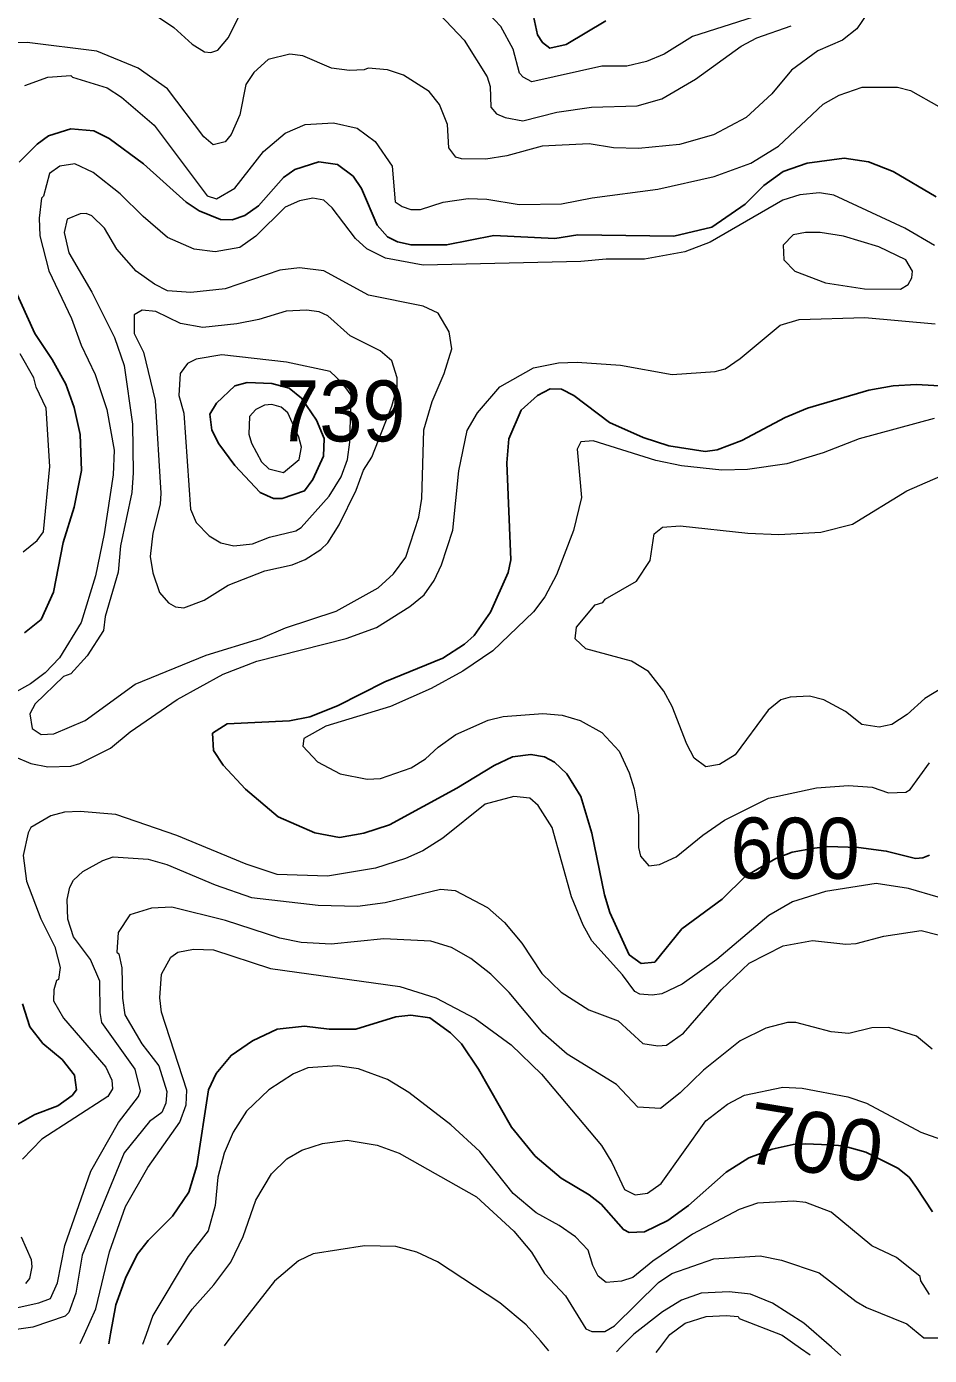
# Model space of a CAD drawing. Extents: x 673.3 to 698.5, y 6984.3 to 7012.3.
# Drawn here: x 695.588 to 696.773, y 6984.271 to 6986.015 of the extents above; entities that cross this region are included whole.
import ezdxf
from ezdxf.enums import TextEntityAlignment as Align

# ---------------------------------------------------------------- set-up
doc = ezdxf.new("R2010")
doc.units = 0
doc.header["$LTSCALE"] = 0.032
doc.layers.add('1', color=7, linetype='Continuous', lineweight=25)
doc.layers.add('2', color=7, linetype='Continuous', lineweight=13)
doc.layers.add('21', color=7, linetype='Continuous')
doc.layers.add('61', color=7, linetype='Continuous')

msp = doc.modelspace()

# ---------------------------------------------------------------- linework, layer by layer
at = {"layer": '1'}
for points in [[(696.2469, 6986.0598), (696.2588, 6986.0042), (696.2653, 6985.9943), (696.2751, 6985.987), (696.2963, 6985.9918), (696.3486, 6986.0229)], [(696.7822, 6985.7918), (696.7259, 6985.825), (696.6936, 6985.8378), (696.6613, 6985.8427), (696.6131, 6985.8361), (696.5815, 6985.825), (696.5562, 6985.8067), (696.5313, 6985.7822), (696.4877, 6985.7521), (696.4377, 6985.7401), (696.3118, 6985.7417), (696.2818, 6985.7369), (696.2014, 6985.7409), (696.1395, 6985.7287), (696.0929, 6985.7287), (696.0751, 6985.7325), (696.0619, 6985.7392), (696.0484, 6985.7546), (696.0276, 6985.8025), (696.0168, 6985.8191), (695.9963, 6985.8343), (695.9718, 6985.8377), (695.9402, 6985.8275), (695.9254, 6985.8172), (695.8928, 6985.7798), (695.8746, 6985.7672), (695.858, 6985.7614), (695.8425, 6985.7621), (695.8146, 6985.7732), (695.7978, 6985.7848), (695.7414, 6985.8349), (695.6965, 6985.8681), (695.6764, 6985.8785), (695.646, 6985.8811), (695.6171, 6985.872), (695.6018, 6985.861), (695.5783, 6985.8373)], [(695.5637, 6985.6908), (695.599, 6985.6125), (695.6218, 6985.5783), (695.6397, 6985.5458), (695.6506, 6985.5151), (695.6586, 6985.48), (695.6602, 6985.4328), (695.6505, 6985.3845), (695.636, 6985.3383), (695.6233, 6985.2729), (695.6073, 6985.2371), (695.5854, 6985.2194)], [(696.4311, 6985.4649), (696.4789, 6985.4576), (696.4946, 6985.4599), (696.5269, 6985.4719), (696.5842, 6985.5022), (696.6132, 6985.5143), (696.6939, 6985.5382), (696.7259, 6985.5438), (696.7558, 6985.5454), (696.8416, 6985.5408)], [(696.7735, 6984.9276), (696.7647, 6984.9244), (696.7553, 6984.9235), (696.7167, 6984.9332), (696.6802, 6984.9379), (696.6397, 6984.939), (696.6226, 6984.9369), (696.5933, 6984.9317), (696.5719, 6984.9236), (696.5321, 6984.9001), (696.5013, 6984.8702), (696.4483, 6984.831), (696.4128, 6984.7875), (696.395, 6984.7857), (696.3793, 6984.7971), (696.354, 6984.8526), (696.3468, 6984.8757), (696.3303, 6984.9565), (696.3156, 6985.005), (696.2973, 6985.0346), (696.2813, 6985.0497), (696.2681, 6985.057), (696.2503, 6985.0601), (696.2259, 6985.0567), (696.202, 6985.0456), (696.1528, 6985.0158), (696.0646, 6984.9678), (696.031, 6984.9568), (695.9991, 6984.951), (695.9666, 6984.9569), (695.9182, 6984.9782), (695.8754, 6985.0143), (695.8461, 6985.046), (695.8337, 6985.0651), (695.8323, 6985.0879), (695.8515, 6985.1), (695.9333, 6985.1041), (695.9599, 6985.1092), (695.9965, 6985.1236), (696.0584, 6985.1554), (696.1346, 6985.1862), (696.1629, 6985.2046), (696.1758, 6985.2159), (696.197, 6985.2469), (696.2202, 6985.2989), (696.2237, 6985.3155), (696.2188, 6985.4428), (696.2213, 6985.4741), (696.2374, 6985.5118), (696.259, 6985.531), (696.2754, 6985.5398), (696.2904, 6985.5395), (696.3066, 6985.5312), (696.3535, 6985.4956), (696.3976, 6985.4759), (696.4311, 6985.4649)], [(695.5829, 6984.7325), (695.5923, 6984.7025), (695.6096, 6984.6805), (695.6347, 6984.6596), (695.6512, 6984.639), (695.6536, 6984.6198), (695.6479, 6984.6122), (695.629, 6984.5987), (695.5989, 6984.5876), (695.5684, 6984.57)], [(695.696, 6984.2865), (695.6984, 6984.2996), (695.7054, 6984.3375), (695.718, 6984.3727), (695.7331, 6984.4037), (695.7479, 6984.4222), (695.7797, 6984.4539), (695.8011, 6984.4854), (695.8118, 6984.5201), (695.827, 6984.6199), (695.8368, 6984.6412), (695.8565, 6984.6651), (695.8847, 6984.6842), (695.917, 6984.6994), (695.9528, 6984.7034), (695.9854, 6984.6993), (696.0202, 6984.6993), (696.073, 6984.7156), (696.0924, 6984.718), (696.1176, 6984.7145), (696.1445, 6984.6946), (696.159, 6984.68), (696.1815, 6984.6469), (696.2246, 6984.571), (696.2556, 6984.533), (696.2899, 6984.5041), (696.3268, 6984.4821), (696.3423, 6984.4698), (696.3717, 6984.4365), (696.3791, 6984.4324), (696.3993, 6984.4337), (696.4301, 6984.4484), (696.4572, 6984.4679), (696.5066, 6984.5116), (696.5364, 6984.5307), (696.567, 6984.5418), (696.5945, 6984.5481), (696.6107, 6984.5489), (696.642, 6984.5478), (696.6602, 6984.5462), (696.6897, 6984.5382), (696.7321, 6984.5172), (696.7468, 6984.5051), (696.7564, 6984.4917), (696.7773, 6984.4599)]]:
    msp.add_lwpolyline(points, dxfattribs=at)
msp.add_lwpolyline([(695.9103, 6985.5469), (695.9327, 6985.5406), (695.9492, 6985.5275), (695.9687, 6985.4985), (695.9786, 6985.4746), (695.9778, 6985.4514), (695.964, 6985.4207), (695.9531, 6985.4061), (695.9235, 6985.3957), (695.9124, 6985.3958), (695.8949, 6985.4036), (695.8613, 6985.4392), (695.8403, 6985.4676), (695.8314, 6985.4855), (695.8288, 6985.5065), (695.8376, 6985.5208), (695.8614, 6985.5438), (695.8776, 6985.5479)], close=True, dxfattribs=at)
at = {"layer": '2'}
for points in [[(695.7585, 6986.0294), (695.7813, 6986.0139), (695.8057, 6985.9919), (695.8216, 6985.982), (695.83, 6985.9812), (695.8392, 6985.9843), (695.853, 6986.0008), (695.8856, 6986.0665)], [(696.6978, 6986.0409), (696.6782, 6986.0122), (696.6592, 6985.9973), (696.6268, 6985.9835), (696.5923, 6985.9579), (696.5667, 6985.9269), (696.5327, 6985.8958), (696.4898, 6985.8731), (696.4451, 6985.8604), (696.3913, 6985.855), (696.3585, 6985.8561), (696.3265, 6985.8615), (696.265, 6985.8581), (696.2186, 6985.8457), (696.1909, 6985.8411), (696.1591, 6985.8415), (696.1517, 6985.8439), (696.1426, 6985.856), (696.1405, 6985.8865), (696.1303, 6985.9131), (696.1168, 6985.93), (696.083, 6985.9513), (696.0619, 6985.9583), (696.0366, 6985.9608), (696.0312, 6985.9584), (696.0119, 6985.9576), (695.9886, 6985.9607), (695.9509, 6985.977), (695.9336, 6985.9788), (695.9053, 6985.9721), (695.8863, 6985.955), (695.876, 6985.9393), (695.8679, 6985.8992), (695.8567, 6985.8734), (695.8488, 6985.8638), (695.8331, 6985.8599), (695.8206, 6985.8704), (695.773, 6985.9336), (695.7346, 6985.9606), (695.6802, 6985.9828), (695.5891, 6985.9943), (695.5616, 6985.9935)], [(696.1225, 6986.04), (696.1628, 6985.9972), (696.1927, 6985.9494), (696.1968, 6985.9364), (696.1975, 6985.9094), (696.2051, 6985.9007), (696.2162, 6985.8957), (696.2395, 6985.8916), (696.2842, 6985.9028), (696.3298, 6985.9094), (696.3896, 6985.9112), (696.4221, 6985.9205), (696.4664, 6985.9462), (696.5264, 6985.9896), (696.5468, 6986.0006), (696.592, 6986.016)], [(696.425, 6985.9789), (696.4021, 6985.9694), (696.3763, 6985.9633), (696.3432, 6985.9632), (696.2515, 6985.9429), (696.24, 6985.9489), (696.2354, 6985.9541), (696.227, 6985.9856), (696.2108, 6986.0151), (696.1941, 6986.0326)], [(696.5421, 6986.0275), (696.4623, 6986.0023), (696.425, 6985.9789)], [(695.5859, 6985.9378), (695.6159, 6985.949), (695.646, 6985.951), (695.6482, 6985.9486), (695.6938, 6985.9346), (695.7129, 6985.9227), (695.7556, 6985.8856), (695.8254, 6985.7929), (695.8374, 6985.7891), (695.8616, 6985.8032), (695.8991, 6985.8514), (695.9275, 6985.8754), (695.9539, 6985.8866), (695.991, 6985.889), (696.0223, 6985.8819), (696.0456, 6985.8644), (696.0681, 6985.8321), (696.0722, 6985.7852), (696.081, 6985.7789), (696.0927, 6985.7752), (696.1051, 6985.7753), (696.1352, 6985.7849), (696.168, 6985.7897), (696.1925, 6985.7889), (696.2349, 6985.7817), (696.2903, 6985.7825), (696.3307, 6985.7906), (696.417, 6985.802), (696.491, 6985.8184), (696.5389, 6985.8361), (696.5754, 6985.8584), (696.6339, 6985.9135), (696.6551, 6985.9252)], [(696.6551, 6985.9252), (696.6853, 6985.9355), (696.7314, 6985.9355), (696.7485, 6985.9314), (696.7856, 6985.9103)], [(696.7801, 6985.7277), (696.741, 6985.7505), (696.6478, 6985.7939), (696.629, 6985.7971), (696.6034, 6985.7945), (696.581, 6985.7872), (696.4857, 6985.7322), (696.4525, 6985.7197), (696.3994, 6985.71), (696.349, 6985.71), (696.3159, 6985.7068), (696.1088, 6985.7019), (696.0595, 6985.7112), (696.0346, 6985.7235), (696.0199, 6985.7369), (695.9891, 6985.7775), (695.9784, 6985.7873), (695.9639, 6985.7898), (695.9466, 6985.7867), (695.9274, 6985.7783), (695.8891, 6985.74), (695.868, 6985.7252), (695.8358, 6985.7198), (695.8082, 6985.7232), (695.7733, 6985.7384), (695.741, 6985.7658), (695.7111, 6985.7958), (695.6756, 6985.8239), (695.6515, 6985.8352), (695.6318, 6985.8321), (695.6182, 6985.8226), (695.6104, 6985.7925), (695.6079, 6985.7901), (695.6047, 6985.7637), (695.6056, 6985.7407), (695.6172, 6985.6947), (695.647, 6985.6321), (695.6596, 6985.5971), (695.678, 6985.5585), (695.6936, 6985.5127), (695.7033, 6985.4594), (695.7017, 6985.4269), (695.6901, 6985.3494), (695.6788, 6985.2944), (695.6596, 6985.2333), (695.6314, 6985.1869), (695.6124, 6985.1672), (695.5932, 6985.1525), (695.5706, 6985.1399)], [(695.5733, 6985.0567), (695.5936, 6985.048), (695.616, 6985.0438), (695.646, 6985.0446), (695.658, 6985.0479), (695.6984, 6985.0683), (695.7241, 6985.0898), (695.7858, 6985.1319), (695.846, 6985.1653), (695.8906, 6985.1822), (696.0077, 6985.2123), (696.0477, 6985.2267), (696.0912, 6985.2541), (696.1099, 6985.2696), (696.1232, 6985.2881), (696.133, 6985.3089), (696.1478, 6985.3544), (696.1554, 6985.432), (696.1666, 6985.485), (696.1799, 6985.5084), (696.2092, 6985.5423), (696.2538, 6985.5674), (696.2864, 6985.5739), (696.3109, 6985.5748), (696.3677, 6985.5708), (696.4355, 6985.5585), (696.4919, 6985.5626), (696.5052, 6985.5661), (696.525, 6985.5794), (696.5775, 6985.6233), (696.6024, 6985.6309), (696.6886, 6985.6335), (696.7808, 6985.6253)], [(695.5838, 6985.3258), (695.6018, 6985.3406), (695.6103, 6985.3523), (695.6186, 6985.438), (695.6137, 6985.5145), (695.6007, 6985.5419), (695.5975, 6985.5542), (695.5797, 6985.5856)], [(696.7794, 6985.5007), (696.6811, 6985.4743), (696.6339, 6985.456), (696.5864, 6985.4413), (696.5346, 6985.4339), (696.5008, 6985.4331), (696.448, 6985.4387), (696.4141, 6985.4459), (696.3321, 6985.4717), (696.3158, 6985.4704), (696.3109, 6985.4607), (696.3167, 6985.3972), (696.3061, 6985.3539), (696.2838, 6985.2958), (696.2685, 6985.267), (696.2536, 6985.2472), (696.2002, 6985.1961), (696.161, 6985.1692), (696.1191, 6985.1465), (696.0659, 6985.1231), (695.9808, 6985.097), (695.9522, 6985.0807), (695.9509, 6985.0707), (695.9699, 6985.0502), (695.9997, 6985.0347), (696.0354, 6985.0276), (696.0527, 6985.0284), (696.0929, 6985.0423), (696.1119, 6985.0543), (696.1285, 6985.0696), (696.1518, 6985.086), (696.1942, 6985.105), (696.2137, 6985.1098), (696.2659, 6985.1139), (696.2911, 6985.1114), (696.3147, 6985.1046), (696.3432, 6985.0888), (696.3662, 6985.0642), (696.3791, 6985.036), (696.3857, 6985.0148), (696.3914, 6984.9808), (696.3915, 6984.9377), (696.3939, 6984.9266), (696.4052, 6984.9136), (696.4192, 6984.9154), (696.4409, 6984.9256), (696.4758, 6984.9541), (696.5045, 6984.9736), (696.5623, 6985.0024), (696.6252, 6985.0161), (696.6673, 6985.0194), (696.6983, 6985.017), (696.7197, 6985.0096), (696.7424, 6985.0105), (696.7483, 6985.0138), (696.7736, 6985.0489)], [(696.7919, 6985.1482), (696.7672, 6985.1335), (696.7443, 6985.1124), (696.7239, 6985.0993), (696.7075, 6985.096), (696.6846, 6985.0995), (696.6633, 6985.1164), (696.6348, 6985.1318), (696.616, 6985.1366), (696.5906, 6985.1352), (696.5782, 6985.1318), (696.5616, 6985.1179), (696.5185, 6985.0595), (696.4977, 6985.0468), (696.48, 6985.0438), (696.4644, 6985.055), (696.4548, 6985.0734), (696.4357, 6985.1231), (696.4248, 6985.1432), (696.4048, 6985.169), (696.3823, 6985.1823), (696.3225, 6985.1985), (696.3085, 6985.2119), (696.3101, 6985.227), (696.3345, 6985.2563), (696.3448, 6985.2596), (696.3479, 6985.2638), (696.3888, 6985.2873), (696.4069, 6985.3143), (696.4121, 6985.3497), (696.423, 6985.3583), (696.4463, 6985.3598), (696.535, 6985.3504), (696.5757, 6985.3485), (696.6307, 6985.3517), (696.6722, 6985.3623), (696.7439, 6985.4061), (696.805, 6985.4325)], [(696.7849, 6984.8728), (696.746, 6984.8841), (696.7035, 6984.8907), (696.6369, 6984.8802), (696.5936, 6984.8666), (696.5627, 6984.8485), (696.4945, 6984.7909), (696.449, 6984.7587), (696.4222, 6984.746), (696.4095, 6984.7441), (696.3933, 6984.7455), (696.3867, 6984.749), (696.3705, 6984.7708), (696.3303, 6984.8154), (696.3187, 6984.8359), (696.3034, 6984.8731), (696.2781, 6984.9643), (696.2597, 6984.9931), (696.2489, 6985.0024), (696.2279, 6985.0047), (696.1903, 6984.9949), (696.1347, 6984.95), (696.1084, 6984.9335), (696.0856, 6984.9235), (696.046, 6984.9108), (695.9831, 6984.9004), (695.9169, 6984.9025), (695.8763, 6984.9158), (695.7854, 6984.9538), (695.7052, 6984.981), (695.6584, 6984.9852), (695.638, 6984.9843), (695.6199, 6984.9795), (695.5936, 6984.9641), (695.59, 6984.9571), (695.5837, 6984.9275), (695.5881, 6984.8937), (695.607, 6984.8441), (695.6252, 6984.8074), (695.6323, 6984.7805), (695.63, 6984.7648), (695.6275, 6984.7634), (695.6237, 6984.7512), (695.6236, 6984.7368), (695.6368, 6984.7139), (695.692, 6984.6494), (695.7001, 6984.6327), (695.7009, 6984.6211), (695.6949, 6984.6109), (695.6083, 6984.5553), (695.5828, 6984.5289)], [(695.5402, 6984.3263), (695.6043, 6984.3402), (695.6195, 6984.3461), (695.6285, 6984.3665), (695.6382, 6984.4154), (695.6725, 6984.5131), (695.7086, 6984.5769), (695.7351, 6984.6109), (695.7375, 6984.6186), (695.7307, 6984.647), (695.6871, 6984.7083), (695.6846, 6984.7212), (695.6845, 6984.7625), (695.6721, 6984.7907), (695.6497, 6984.8205), (695.6422, 6984.8438), (695.6415, 6984.8698), (695.6447, 6984.8856), (695.6497, 6984.8949), (695.6621, 6984.9064), (695.6881, 6984.9209), (695.7018, 6984.9256), (695.7476, 6984.9224), (695.7724, 6984.9157), (695.8358, 6984.8888), (695.8835, 6984.8721), (695.9707, 6984.8621), (696.0226, 6984.8607), (696.0587, 6984.8655), (696.1317, 6984.8833), (696.1507, 6984.8816), (696.1934, 6984.8591), (696.2155, 6984.8394), (696.2385, 6984.8123), (696.2644, 6984.7724), (696.2898, 6984.7478), (696.3263, 6984.7249), (696.3648, 6984.7105), (696.3973, 6984.6808), (696.417, 6984.6774), (696.4283, 6984.6783), (696.4507, 6984.6942), (696.4999, 6984.7509), (696.5367, 6984.786), (696.5813, 6984.8088), (696.6197, 6984.8158), (696.6637, 6984.8109), (696.677, 6984.8117), (696.7134, 6984.8215), (696.7624, 6984.8288), (696.8073, 6984.8175)], [(696.777, 6984.6732), (696.7563, 6984.6903), (696.72, 6984.7017), (696.698, 6984.7011), (696.6675, 6984.6937), (696.6445, 6984.6961), (696.5978, 6984.7082), (696.587, 6984.7082), (696.5585, 6984.7009), (696.5248, 6984.6842), (696.477, 6984.6455), (696.4463, 6984.6158), (696.4203, 6984.5954), (696.3905, 6984.597), (696.3627, 6984.627), (696.2978, 6984.6667), (696.2665, 6984.694), (696.2218, 6984.7475), (696.1978, 6984.7717), (696.1714, 6984.7923), (696.1458, 6984.8067), (696.1187, 6984.8149), (696.0571, 6984.8181), (695.9878, 6984.8109), (695.9487, 6984.8134), (695.9206, 6984.8189), (695.8493, 6984.842), (695.7789, 6984.8597), (695.7522, 6984.8581), (695.7236, 6984.8493), (695.7083, 6984.8262), (695.7066, 6984.8006), (695.7091, 6984.7982), (695.713, 6984.7799), (695.714, 6984.7402), (695.7171, 6984.7183), (695.7395, 6984.6801), (695.7619, 6984.6512), (695.7723, 6984.6175), (695.771, 6984.6022), (695.7658, 6984.5901), (695.7494, 6984.5784), (695.7162, 6984.537), (695.6612, 6984.4028), (695.6528, 6984.353), (695.6436, 6984.3277), (695.6388, 6984.323), (695.5965, 6984.3086), (695.557, 6984.3028)], [(695.6586, 6984.2871), (695.6641, 6984.2993), (695.679, 6984.3326), (695.6969, 6984.4073), (695.7178, 6984.4669), (695.7475, 6984.5178), (695.7893, 6984.5774), (695.7976, 6984.6002), (695.7986, 6984.6192), (695.7651, 6984.7219), (695.7629, 6984.7404), (695.7652, 6984.7716), (695.7776, 6984.7938), (695.7866, 6984.8003), (695.8074, 6984.8043), (695.8336, 6984.8035), (695.9082, 6984.7792), (696.0782, 6984.7555), (696.1255, 6984.7407), (696.1771, 6984.7133), (696.2243, 6984.6791), (696.2642, 6984.6402), (696.3428, 6984.5468), (696.3563, 6984.5245), (696.373, 6984.4892), (696.3869, 6984.4819), (696.4034, 6984.4842), (696.4212, 6984.497), (696.4798, 6984.5791), (696.5085, 6984.6011), (696.5307, 6984.6129), (696.5809, 6984.6235), (696.6064, 6984.6219), (696.6662, 6984.6105), (696.6906, 6984.6023), (696.762, 6984.5641), (696.7878, 6984.5553)], [(696.7737, 6984.3514), (696.7621, 6984.369), (696.7613, 6984.375), (696.73, 6984.3998), (696.6976, 6984.4153), (696.6445, 6984.4592), (696.6111, 6984.472), (696.5948, 6984.4737), (696.5476, 6984.4713), (696.5235, 6984.4627), (696.4624, 6984.4305), (696.4101, 6984.3949), (696.384, 6984.3737), (696.3692, 6984.3686), (696.3491, 6984.3671), (696.3387, 6984.3751), (696.3314, 6984.3895), (696.3255, 6984.4093), (696.3089, 6984.4268), (696.2875, 6984.4418), (696.2569, 6984.4584), (696.2269, 6984.4837), (696.1832, 6984.5387), (696.1453, 6984.5741), (696.0899, 6984.6164), (696.0619, 6984.6332), (696.024, 6984.6473), (695.9961, 6984.6513), (695.9574, 6984.6488), (695.9385, 6984.6409), (695.9061, 6984.6199), (695.8767, 6984.5918), (695.8593, 6984.5644), (695.8476, 6984.5369), (695.8394, 6984.5052), (695.8359, 6984.4682), (695.8263, 6984.4349), (695.8004, 6984.4011), (695.7537, 6984.3237), (695.7449, 6984.2987), (695.7404, 6984.2858)], [(695.773, 6984.2853), (695.7805, 6984.2961), (695.8057, 6984.3322), (695.834, 6984.3641), (695.8564, 6984.3939), (695.8723, 6984.4275), (695.8889, 6984.4752), (695.9095, 6984.5098), (695.93, 6984.5293), (695.9493, 6984.5405), (695.9767, 6984.5494), (696.0089, 6984.5536), (696.0484, 6984.5471), (696.0774, 6984.5367), (696.1787, 6984.4796), (696.2279, 6984.4344), (696.2508, 6984.4068), (696.2681, 6984.3787), (696.2955, 6984.3497), (696.3222, 6984.3062), (696.33, 6984.3028), (696.3472, 6984.3027), (696.3599, 6984.3102), (696.4178, 6984.3672), (696.4352, 6984.3787), (696.4903, 6984.398), (696.5512, 6984.4021), (696.5794, 6984.3964), (696.6288, 6984.3799), (696.6771, 6984.3422), (696.6906, 6984.3343), (696.7439, 6984.3126), (696.766, 6984.2945), (696.7858, 6984.2944)], [(695.5811, 6984.4268), (695.5941, 6984.3972), (695.595, 6984.3874), (695.5918, 6984.3722), (695.5865, 6984.3655)], [(696.2739, 6984.2774), (696.2626, 6984.2904), (696.2442, 6984.3116), (696.2094, 6984.3405), (696.1274, 6984.3941), (696.1004, 6984.407), (696.073, 6984.4142), (696.0317, 6984.4151), (695.9645, 6984.4047), (695.945, 6984.3954), (695.9136, 6984.3689), (695.8549, 6984.2938), (695.8473, 6984.2841)], [(696.6573, 6984.2713), (696.6447, 6984.2822), (696.6087, 6984.3135), (696.5672, 6984.3399), (696.5386, 6984.3516), (696.5105, 6984.3549), (696.4737, 6984.3532), (696.448, 6984.3436), (696.4229, 6984.3283), (696.3854, 6984.299), (696.3688, 6984.2824), (696.3624, 6984.276)], [(696.4147, 6984.2751), (696.4195, 6984.2814), (696.4327, 6984.2986), (696.4529, 6984.3135), (696.4805, 6984.3223), (696.5064, 6984.3239), (696.5224, 6984.3222), (696.5237, 6984.3199), (696.5799, 6984.2977), (696.6041, 6984.2808), (696.6168, 6984.2719)]]:
    msp.add_lwpolyline(points, dxfattribs=at)
for points in [[(696.0499, 6985.2785), (696.0696, 6985.2968), (696.086, 6985.3191), (696.1031, 6985.3713), (696.1072, 6985.3957), (696.1097, 6985.4858), (696.1204, 6985.5232), (696.1365, 6985.5601), (696.1463, 6985.5925), (696.1429, 6985.6148), (696.1283, 6985.639), (696.1086, 6985.6481), (696.0372, 6985.6628), (695.9783, 6985.6945), (695.9466, 6985.6985), (695.9205, 6985.6955), (695.8489, 6985.6709), (695.8039, 6985.666), (695.7732, 6985.6685), (695.7559, 6985.6773), (695.7322, 6985.6941), (695.7064, 6985.723), (695.6904, 6985.7505), (695.674, 6985.7669), (695.6662, 6985.7701), (695.6583, 6985.7695), (695.6415, 6985.7626), (695.6374, 6985.7448), (695.6434, 6985.7184), (695.6737, 6985.6666), (695.7035, 6985.6071), (695.7162, 6985.5706), (695.7271, 6985.4934), (695.728, 6985.4296), (695.7261, 6985.4036), (695.7115, 6985.3337), (695.7082, 6985.2993), (695.6912, 6985.2412), (695.6889, 6985.2228), (695.6678, 6985.1892), (695.646, 6985.1659), (695.6367, 6985.1623), (695.5992, 6985.1262), (695.5926, 6985.1135), (695.5954, 6985.094), (695.6072, 6985.0861), (695.6238, 6985.087), (695.6649, 6985.1047), (695.7308, 6985.152), (695.824, 6985.1902), (695.8951, 6985.2122), (695.9281, 6985.2262), (695.9946, 6985.2482)], [(696.6881, 6985.6712), (696.7353, 6985.6708), (696.7457, 6985.6766), (696.7505, 6985.6853), (696.7513, 6985.6944), (696.7423, 6985.7091), (696.7069, 6985.7261), (696.6608, 6985.7401), (696.6299, 6985.745), (696.6108, 6985.745), (696.5947, 6985.7418), (696.5813, 6985.7284), (696.5821, 6985.7092), (696.5966, 6985.6942), (696.6369, 6985.679)], [(695.901, 6985.3008), (695.937, 6985.309), (695.9539, 6985.3157), (695.9745, 6985.3288), (695.9834, 6985.3378), (695.9984, 6985.3612), (696.0208, 6985.4068), (696.0306, 6985.4329), (696.0415, 6985.45), (696.0678, 6985.5169), (696.0746, 6985.542), (696.0747, 6985.5544), (696.0676, 6985.5765), (696.0525, 6985.5896), (696.0131, 6985.6093), (695.9835, 6985.6358), (695.9721, 6985.6407), (695.9558, 6985.6432), (695.9287, 6985.6416), (695.893, 6985.6307), (695.8641, 6985.6249), (695.8193, 6985.6203), (695.7904, 6985.6256), (695.7579, 6985.6415), (695.74, 6985.6431), (695.7293, 6985.6371), (695.7294, 6985.6124), (695.7418, 6985.5879), (695.757, 6985.5246), (695.7644, 6985.4028), (695.7634, 6985.3885), (695.7539, 6985.3503), (695.7505, 6985.3198), (695.7538, 6985.2982), (695.7625, 6985.2725), (695.7744, 6985.2588), (695.7838, 6985.2538), (695.7947, 6985.2524), (695.8212, 6985.2623), (695.8526, 6985.2821)], [(695.86, 6985.3338), (695.8847, 6985.3363), (695.9069, 6985.3451), (695.9414, 6985.3534), (695.9484, 6985.3576), (695.9855, 6985.3991), (696.001, 6985.4243), (696.0094, 6985.4471), (696.0127, 6985.4699), (696.0144, 6985.5313), (696.0026, 6985.5476), (695.9866, 6985.5624), (695.9295, 6985.5748), (695.8444, 6985.5846), (695.8106, 6985.5787), (695.7995, 6985.5731), (695.7898, 6985.5601), (695.7881, 6985.5311), (695.7945, 6985.508), (695.8033, 6985.382), (695.8106, 6985.3644), (695.8278, 6985.3469), (695.8432, 6985.3379)], [(695.946, 6985.447), (695.9491, 6985.4634), (695.9457, 6985.4762), (695.931, 6985.5083), (695.9224, 6985.5158), (695.9102, 6985.5194), (695.9004, 6985.5185), (695.889, 6985.5128), (695.8809, 6985.5036), (695.8801, 6985.4801), (695.8835, 6985.4686), (695.8967, 6985.4442), (695.9063, 6985.435), (695.9254, 6985.4299)]]:
    msp.add_lwpolyline(points, close=True, dxfattribs=at)

# ---------------------------------------------------------------- texts
at = {"layer": '21', "width": 0.95}
msp.add_text('739', height=0.08, dxfattribs=at).set_placement((695.916, 6985.4708))
at = {"layer": '61', "width": 0.95}
msp.add_text('600', height=0.08, rotation=359.816, dxfattribs=at).set_placement((696.5969, 6984.897), align=Align.CENTER)
at = {"layer": '61'}
msp.add_text('700', height=0.08, rotation=350.744, dxfattribs=at).set_placement((696.6166, 6984.5114), align=Align.CENTER)

doc.saveas('drawing.dxf')
